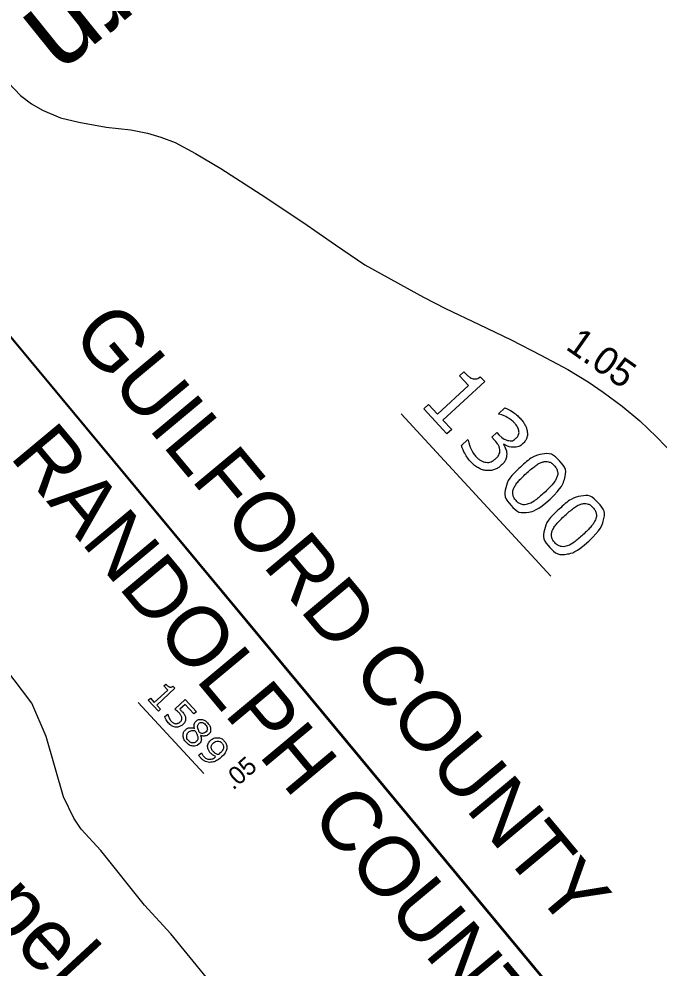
# Model space of a CAD drawing. Extents: x 1695041 to 1706254, y 786537 to 798223.
# Drawn here: x 1703111 to 1703245.1, y 796662.3 to 796861.2 of the extents above; entities that cross this region are included whole.
import ezdxf

# ---------------------------------------------------------------- set-up
doc = ezdxf.new("R2010")
doc.units = 0
doc.layers.add('Default', color=7, linetype='Continuous')
doc.layers.add('Old_Level_32', color=7, linetype='Continuous')

msp = doc.modelspace()

# ---------------------------------------------------------------- linework, layer by layer
at = {"layer": 'Default'}
for p, q in [((1703082.86, 796826.28), (1703289.9, 796576.76)), ((1703191.06, 796778.47), (1703222.44, 796744.47)), ((1703135.99, 796718.01), (1703149.71, 796703.14))]:
    msp.add_line(p, q, dxfattribs=at)
for points in [[(1702807.76, 797162.38), (1703001.1, 796924.8), (1703349.84, 796504.53)], [(1702807.76, 797162.38), (1703001.1, 796924.8), (1703349.84, 796504.53)], [(1703083.28, 796825.8), (1703083.28, 796825.8), (1703172.11, 796719.11), (1703302.41, 796562.08)], [(1703083.28, 796825.8), (1703083.28, 796825.8), (1703172.11, 796719.11), (1703302.41, 796562.08)], [(1703302.56, 796561.89), (1703172.11, 796719.11), (1703083.28, 796825.8)], [(1703302.56, 796561.89), (1703172.11, 796719.11), (1703083.28, 796825.8)], [(1703200.69, 796774.27), (1703195.84, 796779.52), (1703196.83, 796780.44), (1703198.7, 796778.42), (1703205.2, 796784.42), (1703203.34, 796786.44), (1703204.23, 796787.26)], [(1703207.67, 796786.25), (1703208.6, 796785.24), (1703199.85, 796777.16), (1703201.68, 796775.18), (1703200.69, 796774.27)], [(1703211.55, 796778.44), (1703211.49, 796778.51), (1703212.85, 796779.76)], [(1703210.63, 796772.99), (1703210.09, 796773.58), (1703211.17, 796774.57), (1703211.59, 796774.12)], [(1703203.7, 796771.83), (1703205.06, 796773.08), (1703205.15, 796772.99)], [(1703212.64, 796772.16), (1703212.55, 796772.08)], [(1703140.2, 796716.17), (1703138.08, 796718.47), (1703138.51, 796718.87), (1703139.33, 796717.98), (1703142.17, 796720.61), (1703141.36, 796721.49), (1703141.75, 796721.85)], [(1703143.25, 796721.41), (1703143.66, 796720.97), (1703139.84, 796717.44), (1703140.63, 796716.57), (1703140.2, 796716.17)], [(1703143.62, 796716.6), (1703145.8, 796718.61), (1703148.16, 796716.06), (1703147.66, 796715.6), (1703145.81, 796717.61), (1703144.68, 796716.57)], [(1703141.55, 796715.03), (1703142.15, 796715.58), (1703142.19, 796715.54)], [(1703147.76, 796712.53), (1703147.78, 796712.54)], [(1703149.06, 796711.11), (1703149.04, 796711.1)], [(1703148.66, 796706.97), (1703149.21, 796707.48), (1703149.23, 796707.45)]]:
    msp.add_lwpolyline(points, dxfattribs=at)
for points in [[(1703204.23, 796787.26), (1703204.6, 796786.85), (1703205.11, 796786.44), (1703205.61, 796786.04), (1703205.96, 796785.92), (1703206.4, 796785.77), (1703206.81, 796785.83), (1703207.22, 796785.89), (1703207.67, 796786.25)], [(1703212.85, 796779.76), (1703213.5, 796779.51), (1703214.41, 796778.91), (1703215.31, 796778.32), (1703215.98, 796777.59), (1703216.64, 796776.88), (1703217.01, 796776.22), (1703217.38, 796775.56), (1703217.5, 796774.85), (1703217.62, 796774.1), (1703217.4, 796773.44), (1703217.17, 796772.79), (1703216.58, 796772.25), (1703215.77, 796771.5), (1703214.64, 796771.51), (1703213.51, 796771.53), (1703212.64, 796772.16)], [(1703211.59, 796774.12), (1703212.51, 796773.12), (1703213.47, 796772.92), (1703214.43, 796772.71), (1703215.22, 796773.44), (1703215.58, 796773.77), (1703215.7, 796774.16), (1703215.83, 796774.56), (1703215.75, 796774.98), (1703215.66, 796775.42), (1703215.43, 796775.8), (1703215.2, 796776.18), (1703214.83, 796776.59), (1703214.26, 796777.21), (1703213.39, 796777.7), (1703212.52, 796778.19), (1703211.55, 796778.44)], [(1703205.15, 796772.99), (1703205.29, 796772.09), (1703205.74, 796771.12), (1703206.2, 796770.15), (1703206.84, 796769.45), (1703207.22, 796769.04), (1703207.79, 796768.7), (1703208.35, 796768.37), (1703208.88, 796768.33), (1703209.45, 796768.29), (1703209.93, 796768.46), (1703210.41, 796768.64), (1703210.94, 796769.13), (1703211.47, 796769.61), (1703211.66, 796770.09), (1703211.84, 796770.58), (1703211.77, 796771.05), (1703211.7, 796771.53), (1703211.39, 796772.02), (1703211.08, 796772.51), (1703210.63, 796772.99)], [(1703213.21, 796770.09), (1703213.21, 796769.52), (1703212.98, 796768.93), (1703212.74, 796768.33), (1703212.07, 796767.71), (1703211.4, 796767.1), (1703210.62, 796766.83), (1703209.85, 796766.56), (1703209.03, 796766.61), (1703208.12, 796766.68), (1703207.29, 796767.14), (1703206.46, 796767.6), (1703205.74, 796768.39), (1703204.99, 796769.2), (1703204.46, 796770.16), (1703203.93, 796771.12), (1703203.7, 796771.83)], [(1703212.55, 796772.08), (1703212.78, 796771.72), (1703212.99, 796771.16), (1703213.2, 796770.6), (1703213.21, 796770.09)], [(1703222.29, 796760.62), (1703219.67, 796758.2), (1703217.69, 796757.89), (1703215.71, 796757.58), (1703214.13, 796759.3), (1703212.51, 796761.05), (1703213.01, 796763), (1703213.51, 796764.95), (1703216.08, 796767.32), (1703218.67, 796769.71), (1703220.66, 796770.04), (1703222.65, 796770.37), (1703224.25, 796768.64), (1703225.86, 796766.89), (1703225.34, 796764.93), (1703224.83, 796762.96), (1703222.29, 796760.62)], [(1703217.74, 796759.6), (1703218.48, 796759.86), (1703219.27, 796760.44), (1703220.06, 796761.02), (1703221.07, 796761.94), (1703222.06, 796762.86), (1703222.72, 796763.62), (1703223.37, 796764.37), (1703223.67, 796765.08), (1703223.96, 796765.77), (1703223.85, 796766.4), (1703223.74, 796767.03), (1703223.17, 796767.65), (1703222.6, 796768.26), (1703221.98, 796768.42), (1703221.35, 796768.59), (1703220.62, 796768.35), (1703219.93, 796768.12), (1703219.08, 796767.49), (1703218.23, 796766.85), (1703217.3, 796766), (1703216.29, 796765.06), (1703215.67, 796764.35), (1703215.05, 796763.65), (1703214.72, 796762.91), (1703214.41, 796762.23), (1703214.51, 796761.59), (1703214.6, 796760.95), (1703215.2, 796760.29), (1703215.77, 796759.68), (1703216.4, 796759.51), (1703217.02, 796759.34), (1703217.74, 796759.6)], [(1703230.41, 796751.82), (1703227.79, 796749.41), (1703225.81, 796749.09), (1703223.84, 796748.78), (1703222.25, 796750.5), (1703220.64, 796752.25), (1703221.13, 796754.2), (1703221.63, 796756.15), (1703224.2, 796758.52), (1703226.79, 796760.91), (1703228.78, 796761.24), (1703230.77, 796761.57), (1703232.37, 796759.84), (1703233.98, 796758.1), (1703233.47, 796756.13), (1703232.95, 796754.17), (1703230.41, 796751.82)], [(1703225.87, 796750.8), (1703226.6, 796751.06), (1703227.39, 796751.64), (1703228.18, 796752.22), (1703229.19, 796753.15), (1703230.18, 796754.06), (1703230.84, 796754.82), (1703231.49, 796755.57), (1703231.79, 796756.28), (1703232.08, 796756.97), (1703231.97, 796757.6), (1703231.86, 796758.23), (1703231.29, 796758.85), (1703230.72, 796759.46), (1703230.1, 796759.63), (1703229.48, 796759.79), (1703228.74, 796759.55), (1703228.06, 796759.33), (1703227.2, 796758.69), (1703226.35, 796758.05), (1703225.42, 796757.2), (1703224.41, 796756.26), (1703223.79, 796755.55), (1703223.17, 796754.85), (1703222.84, 796754.12), (1703222.53, 796753.43), (1703222.63, 796752.79), (1703222.72, 796752.15), (1703223.33, 796751.5), (1703223.89, 796750.88), (1703224.52, 796750.72), (1703225.15, 796750.55), (1703225.87, 796750.8)], [(1703141.75, 796721.85), (1703141.91, 796721.67), (1703142.13, 796721.49), (1703142.35, 796721.31), (1703142.51, 796721.26), (1703142.7, 796721.2), (1703142.88, 796721.22), (1703143.06, 796721.25), (1703143.25, 796721.41)], [(1703145.29, 796713.36), (1703144.99, 796713.09), (1703144.62, 796712.94), (1703144.25, 796712.8), (1703143.89, 796712.82), (1703143.5, 796712.84), (1703143.14, 796713.03), (1703142.77, 796713.21), (1703142.42, 796713.58), (1703142.1, 796713.93), (1703141.88, 796714.32), (1703141.65, 796714.71), (1703141.55, 796715.03)], [(1703142.19, 796715.54), (1703142.25, 796715.17), (1703142.44, 796714.76), (1703142.63, 796714.35), (1703142.9, 796714.05), (1703143.09, 796713.85), (1703143.32, 796713.71), (1703143.55, 796713.57), (1703143.83, 796713.56), (1703144.07, 796713.54), (1703144.3, 796713.64), (1703144.53, 796713.73), (1703144.76, 796713.94), (1703144.98, 796714.14), (1703145.06, 796714.36), (1703145.14, 796714.57), (1703145.11, 796714.79), (1703145.08, 796715.04), (1703144.93, 796715.29), (1703144.78, 796715.55), (1703144.54, 796715.81), (1703144.31, 796716.06), (1703144.06, 796716.26), (1703143.81, 796716.46), (1703143.62, 796716.6)], [(1703144.68, 796716.57), (1703144.81, 796716.45), (1703144.93, 796716.33), (1703145.06, 796716.21), (1703145.14, 796716.11), (1703145.46, 796715.77), (1703145.64, 796715.45), (1703145.82, 796715.14), (1703145.88, 796714.79), (1703145.93, 796714.41), (1703145.8, 796714.06), (1703145.66, 796713.7), (1703145.29, 796713.36)], [(1703147.78, 796712.54), (1703147.64, 796713.05), (1703147.71, 796713.42), (1703147.77, 796713.78), (1703148.1, 796714.08), (1703148.58, 796714.52), (1703149.26, 796714.43), (1703149.94, 796714.33), (1703150.5, 796713.72), (1703151.09, 796713.08), (1703151.13, 796712.42), (1703151.18, 796711.76), (1703150.71, 796711.33), (1703150.42, 796711.06), (1703149.98, 796710.99), (1703149.53, 796710.91), (1703149.06, 796711.11)], [(1703150.19, 796711.88), (1703150.49, 796712.17), (1703150.45, 796712.57), (1703150.42, 796712.97), (1703150.08, 796713.34), (1703149.75, 796713.7), (1703149.36, 796713.77), (1703148.98, 796713.84), (1703148.69, 796713.57), (1703148.49, 796713.38), (1703148.44, 796713.13), (1703148.4, 796712.87), (1703148.5, 796712.53), (1703148.55, 796712.38), (1703148.65, 796712.11), (1703148.75, 796711.83), (1703148.87, 796711.59), (1703149.32, 796711.48), (1703149.62, 796711.56), (1703149.92, 796711.64), (1703150.19, 796711.88)], [(1703148.74, 796709.3), (1703148.19, 796708.79), (1703147.43, 796708.88), (1703146.66, 796708.97), (1703146.06, 796709.62), (1703145.43, 796710.31), (1703145.41, 796711.05), (1703145.38, 796711.79), (1703145.94, 796712.3), (1703146.29, 796712.63), (1703146.77, 796712.69), (1703147.25, 796712.75), (1703147.76, 796712.53)], [(1703148.14, 796709.83), (1703148.41, 796710.07), (1703148.46, 796710.34), (1703148.51, 796710.6), (1703148.36, 796711.08), (1703148.3, 796711.27), (1703148.2, 796711.48), (1703148.11, 796711.69), (1703147.96, 796712.05), (1703147.58, 796712.17), (1703147.2, 796712.11), (1703146.82, 796712.04), (1703146.52, 796711.76), (1703146.13, 796711.41), (1703146.13, 796710.91), (1703146.12, 796710.42), (1703146.5, 796710.01), (1703146.88, 796709.59), (1703147.33, 796709.54), (1703147.77, 796709.49), (1703148.14, 796709.83)], [(1703149.04, 796711.1), (1703149.24, 796710.54), (1703149.18, 796710.1), (1703149.12, 796709.65), (1703148.74, 796709.3)], [(1703149.23, 796707.45), (1703149.27, 796707.33), (1703149.37, 796707.14), (1703149.47, 796706.95), (1703149.64, 796706.77), (1703150.22, 796706.14), (1703150.93, 796706.13), (1703151.63, 796706.12), (1703152.35, 796706.68), (1703151.95, 796706.79), (1703151.66, 796706.96), (1703151.38, 796707.13), (1703151.12, 796707.41), (1703150.88, 796707.67), (1703150.74, 796707.93), (1703150.59, 796708.19), (1703150.54, 796708.54), (1703150.49, 796708.95), (1703150.64, 796709.33), (1703150.79, 796709.7), (1703151.16, 796710.05), (1703151.81, 796710.65), (1703152.62, 796710.6), (1703153.42, 796710.55), (1703153.99, 796709.93), (1703154.27, 796709.62), (1703154.42, 796709.27), (1703154.56, 796708.92), (1703154.55, 796708.55), (1703154.54, 796708.09), (1703154.29, 796707.61), (1703154.04, 796707.14), (1703153.45, 796706.59)], [(1703153.04, 796707.29), (1703153.48, 796707.69), (1703153.66, 796708.03), (1703153.85, 796708.37), (1703153.85, 796708.67), (1703153.85, 796708.92), (1703153.77, 796709.12), (1703153.68, 796709.33), (1703153.52, 796709.51), (1703153.14, 796709.92), (1703152.66, 796709.92), (1703152.19, 796709.92), (1703151.72, 796709.49), (1703151.45, 796709.24), (1703151.35, 796709.01), (1703151.25, 796708.77), (1703151.29, 796708.47), (1703151.32, 796708.26), (1703151.43, 796708.08), (1703151.54, 796707.9), (1703151.72, 796707.71), (1703151.92, 796707.49), (1703152.19, 796707.32), (1703152.46, 796707.14), (1703152.76, 796707.05), (1703152.82, 796707.1), (1703152.89, 796707.15), (1703152.95, 796707.2), (1703153.04, 796707.29)], [(1703153.45, 796706.59), (1703152.89, 796706.08), (1703152.32, 796705.79), (1703151.75, 796705.5), (1703151.19, 796705.46), (1703150.63, 796705.42), (1703150.09, 796705.64), (1703149.55, 796705.87), (1703149.07, 796706.4), (1703148.93, 796706.55), (1703148.83, 796706.69), (1703148.72, 796706.84), (1703148.66, 796706.97)]]:
    msp.add_open_spline(points, degree=3, dxfattribs=at)
at = {"layer": 'Old_Level_32'}
for points in [[(1703108.7, 796847.9), (1703111.32, 796845.23), (1703113.57, 796843.48), (1703115.92, 796842.15), (1703119.66, 796840.51), (1703123.51, 796839.61), (1703129.26, 796838.55), (1703134.42, 796838.02), (1703137.94, 796837.31), (1703140.74, 796836.49), (1703143.68, 796835.38), (1703147.98, 796833.08), (1703153.29, 796829.9), (1703161.71, 796824.49), (1703170.46, 796818.65), (1703177.29, 796813.91), (1703183.49, 796809.71), (1703195.77, 796802.92), (1703200.41, 796800.56), (1703207.41, 796797.19), (1703214.11, 796794), (1703220.37, 796790.82), (1703226.03, 796787.81), (1703230.31, 796785.17), (1703233.41, 796783), (1703237.38, 796780.11), (1703241.12, 796777.01), (1703244.62, 796773.69), (1703250.25, 796767.82)], [(1703153.7, 796656.19), (1703142.82, 796669.52), (1703137.28, 796675.5), (1703128.15, 796686.97), (1703124.02, 796691.44), (1703122.48, 796693.73), (1703120.3, 796698.24), (1703116.65, 796710.86), (1703113.66, 796717.82), (1703107.99, 796725.36), (1703103.17, 796730.27), (1703096.92, 796737.12), (1703083.08, 796754.2)]]:
    msp.add_lwpolyline(points, dxfattribs=at)

# ---------------------------------------------------------------- texts
at = {"layer": 'Default'}
for s, height, rotation, p in [('Southern', 18.015, 218.8645, (1703186.73, 796921.93)), ('GUILFORD COUNTY', 12.6, 309.8165, (1703121.66, 796794.91)), ('1.05', 5.775, 324.968, (1703225.33, 796792.19)), ('RANDOLPH COUNTY', 12.6, 309.8165, (1703108.83, 796769.51)), ('Hope Chapel', 13.102, 312.7091, (1703049.6, 796732.36)), ('.05', 3.789, 41.5429, (1703155.88, 796699.5))]:
    msp.add_text(s, height=height, rotation=rotation, dxfattribs=at).set_placement(p)

doc.saveas('drawing.dxf')
